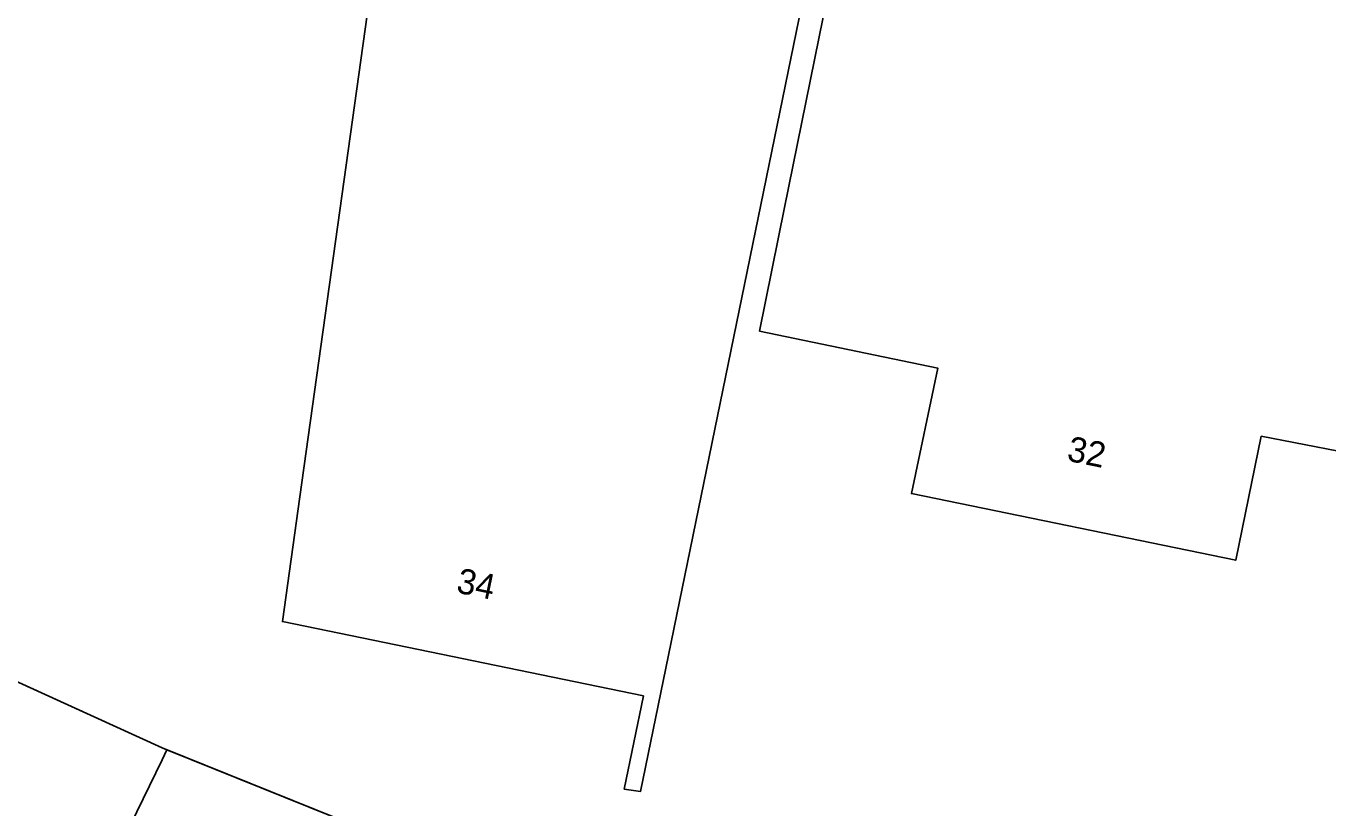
# Model space of a CAD drawing. Extents: x 157692 to 159674, y 381452 to 383291.
# Drawn here: x 158176.3 to 158228, y 381850.5 to 381881.5 of the extents above; entities that cross this region are included whole.
import ezdxf

# ---------------------------------------------------------------- set-up
doc = ezdxf.new("R2010")
doc.units = 0
for name, color, linetype in [('IMGEO_Berm_groen', 7, 'Continuous'), ('IMGEO_Erf', 7, 'Continuous'), ('IMGEO_Hek', 7, 'Continuous'), ('IMGEO_Pand', 7, 'Continuous'), ('IMGEO_Pand_nummerreeks', 7, 'Continuous'), ('IMGEO_Rijbaan_lokaal_open', 7, 'Continuous')]:
    doc.layers.add(name, color=color, linetype=linetype)

msp = doc.modelspace()

# ---------------------------------------------------------------- linework, layer by layer
at = {"layer": 'IMGEO_Berm_groen'}
msp.add_lwpolyline([(158201.637, 381844.863), (158181.907, 381852.815), (158181.717, 381852.408), (158176.956, 381842.64), (158178.653, 381841.845)], dxfattribs=at)
at = {"layer": 'IMGEO_Erf'}
for points in [[(158120.644, 381974.489), (158119.054, 381966.712), (158111.645, 381930.552), (158109.555, 381920.351), (158108.214, 381913.847), (158101.637, 381881.433), (158103.57, 381880.897), (158105.432, 381880.499), (158105.527, 381880.719), (158125.96, 381875.333), (158144.779, 381868.849), (158152.635, 381866.121), (158152.79, 381866.076), (158175.894, 381855.545), (158181.715, 381852.892), (158181.907, 381852.815), (158201.637, 381844.863), (158208.362, 381842.809), (158208.31, 381842.627), (158217.316, 381839.906), (158270.263, 381825.792)], [(158212.684, 381909.652), (158201.697, 381856.053), (158200.693, 381851.154), (158200.049, 381851.25), (158200.81, 381854.948), (158186.49, 381857.896), (158187.182, 381862.848), (158191.444, 381893.334)]]:
    msp.add_lwpolyline(points, dxfattribs=at)
msp.add_lwpolyline([(158238.323, 381904.434), (158231.087, 381869.22), (158230.08, 381864.322), (158225.315, 381865.248), (158224.304, 381860.328), (158211.442, 381862.976), (158212.491, 381867.943), (158205.415, 381869.42), (158206.41, 381874.32), (158213.564, 381909.551)], close=True, dxfattribs=at)
at = {"layer": 'IMGEO_Hek'}
msp.add_lwpolyline([(158152.635, 381866.121), (158152.79, 381866.076), (158181.715, 381852.892), (158201.637, 381844.863)], dxfattribs=at)
at = {"layer": 'IMGEO_Pand'}
for points in [[(158212.684, 381909.652), (158192.825, 381913.715), (158136.166, 381925.258), (158134.023, 381914.791), (158132.884, 381909.227), (158150.883, 381905.602), (158150.089, 381901.741), (158154.699, 381900.804), (158184.121, 381894.823), (158191.444, 381893.334), (158187.182, 381862.848), (158186.49, 381857.896), (158200.81, 381854.948), (158200.049, 381851.25), (158200.693, 381851.154), (158201.697, 381856.053)], [(158224.304, 381860.328), (158225.315, 381865.248), (158230.08, 381864.322), (158231.087, 381869.22), (158238.323, 381904.434), (158213.564, 381909.551), (158206.41, 381874.32), (158205.415, 381869.42), (158212.491, 381867.943), (158211.442, 381862.976)]]:
    msp.add_lwpolyline(points, close=True, dxfattribs=at)
at = {"layer": 'IMGEO_Rijbaan_lokaal_open'}
msp.add_lwpolyline([(158181.717, 381852.408), (158181.907, 381852.815), (158181.715, 381852.892), (158175.894, 381855.545), (158175.726, 381855.243), (158171.542, 381846.928), (158170.769, 381845.392), (158176.956, 381842.64)], close=True, dxfattribs=at)

# ---------------------------------------------------------------- texts
at = {"layer": 'IMGEO_Pand_nummerreeks'}
for s, rotation, p in [('32', 348.3666, (158217.569, 381864.287)), ('34', 348.369, (158193.349, 381859.056))]:
    msp.add_text(s, height=1, rotation=rotation, dxfattribs=at).set_placement(p)

doc.saveas('drawing.dxf')
